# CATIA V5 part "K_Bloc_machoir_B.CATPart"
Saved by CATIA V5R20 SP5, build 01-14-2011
Part number: bloc_machoir_2
Publications: "diam_trou_fourreau"
Bounding box of the stored display mesh (mm): x -55.068 to 17.929, y -56.771 to 28.229, z 0 to 35
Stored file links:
  G:\Khaled_CFAO_2011\SIL\SIL_GR1\mroland\Khaled\CAD_CATIA_Modifie\K_Bloc_machoir_B.CATPart
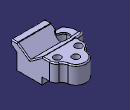
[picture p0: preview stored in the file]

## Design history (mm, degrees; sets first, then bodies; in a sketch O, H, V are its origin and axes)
Parameters
  diam_trou_fourreau = 22 mm
Set1
  Sketch1 on xy-plane, origin (0, 0, 0), H (1, 0, 0), V (0, 1, 0)
    point P1 (-32.0711, 0)
    line L1 (-32.0711, -56.7712) -> (17.9289, -56.7712)
    line L2 (17.9289, -56.7712) -> (17.9289, 0)
    point P4 (17.9289, 0)
    arc A1 centre (7.9289, 0) radius 10 from (17.9289, 0) to (13.0826, 8.5697) ccw
    point P5 (7.9289, 0)
    point P6 (17.9289, 0)
    arc A2 centre (-7.0711, 13.2288) radius 15 from (7.6161, 16.276) to (-21.9589, 15.0594) ccw
    point P7 (-7.0711, 13.2288)
    point P8 (0, 26.4575)
    arc A3 centre (-22.0711, 0) radius 10 from (-26.3136, 9.0554) to (-32.0711, 0) ccw
    point P9 (-22.0711, 0)
    point P10 (-32.0711, 0)
    arc A4 centre (-29.5647, 15.9947) radius 7.6631 from (-21.9589, 15.0594) to (-26.3136, 9.0554) cw
    arc A5 centre (19.1569, 18.6704) radius 11.7865 from (7.6161, 16.276) to (13.0826, 8.5697) ccw
    line L3 (-32.0711, -56.7712) -> (-32.0711, -52.5474)
    arc A6 centre (-35.0711, -32.7737) radius 20 from (-32.0711, -52.5474) to (-32.0711, -13) cw
    point P18 (-35.0711, -32.7737)
    point P19 (-32.0711, -13)
    line L4 (-32.0711, -13) -> (-32.0711, 0)
    distance P9 A3 = 10
    distance P5 A1 = 10
    distance P7 A2 = 15
    distance P7 P9 = 20
    distance P7 P5 = 20
    distance P5 P9 = 30
    distance L1 A2 = 85
    radius A4 = 7.6631
    radius A5 = 11.7865
    radius A6 = 20
    length L4 = 13
    distance P18 L4 = 3
    length L3 = 4.2238
    coincidence: P1 H, P4 H, A1 P6, P6 L2, A2 P8, P8 V, A2 O, A3 P10, P19 L3
    horizontal: L1 H
    vertical: L2 V
    tangency: L2 A1, A4 A2, A4 A3, A5 A2, A5 A1, L3 A3, L4 A3
Body1 (main body)
  Pad1: profile Sketch1, direction (0, 0, 1), length 35
  Sketch2 on end face of Pad1, origin (-8.9228, 9.7204, 35), H (1, 0, 0), V (0, 1, 0)
    point P1 (1.8517, 3.5083)
    reference projected arc E1 centre (1.8517, 3.5083) radius 15 from (16.5389, 6.5556) to (-13.0362, 5.339) ccw from edge [face of Pad1 from Sketch1.A2 | end face of Pad1]
    concentricity: E1 P1
  Hole1: placed by Sketch2, at (-7.0711, 13.2288, 35) direction (0, 0, -1), diameter 10 {= 10mm}, through (limit type 3)
  Sketch3 on end face of Pad1, origin (-21.1049, 2.0333, 35), H (1, 0, 0), V (0, 1, 0)
    point P1 (28.4106, -1.4836)
    reference projected point E1 (14.0338, 11.1955) from axis of face of Hole1
    distance E1 P1 = 19.169
  Hole2: placed by Sketch3, at (7.3057, 0.5497, 35) direction (0, 0, -1), diameter 10, through (limit type 3)
  Sketch4 on end face of Pad1, origin (-9.8751, -18.0882, 35), H (1, 0, 0), V (0, 1, 0)
    point P1 (-12.8071, 19.4905)
    reference projected point E1 (17.1807, 18.6379) from axis of face of Hole2
    reference projected point E2 (2.804, 31.317) from axis of face of Hole1
    distance P1 E1 = 30
    distance P1 E2 = 19.585
    distance P1 H = 19.3485
  Hole3: placed by Sketch4, at (-22.6822, 1.4023, 35) direction (0, 0, -1), diameter 10, through (limit type 3)
  Sketch5 on start face of Pad1, origin (-3.6482, -28.1007, 0), H (1, 0, 0), V (0, -1, 0)
    point P1 (-31.4229, 4.673)
    reference projected arc E1 centre (-31.4229, 4.673) radius 20 from (-28.4229, 24.4468) to (-28.4229, -15.1007) ccw from edge [start face of Pad1 | face of Pad1 from Sketch1.A6]
    concentricity: E1 P1
  Hole4: placed by Sketch5, at (-35.0711, -32.7737, 0) direction (0, 0, 1), diameter 22 {= diam_trou_fourreau}, depth 20
  Sketch6 on start face of Pad1, origin (-39.0223, -19.3557, 0), H (1, 0, 0), V (0, -1, 0)
    point P1 (3.9512, 13.418)
    reference projected circle E1 centre (3.9512, 13.418) radius 11 from edge [face of Hole4 | start face of Pad1]
    concentricity: E1 P1
  Hole5: placed by Sketch6, at (-35.0711, -32.7737, 0) direction (0, 0, 1), diameter 18, through (limit type 3)
  Sketch7 on start face of Pad1, origin (0, 0, 0), H (1, 0, 0), V (0, -1, 0)
    line L1 (-37.0711, 10.7737) -> (22.9289, 10.7737)
    line L2 (22.9289, 10.7737) -> (22.9289, -33.2288)
    line L3 (22.9289, -33.2288) -> (-37.0711, -33.2288)
    line L4 (-37.0711, -33.2288) -> (-37.0711, 10.7737)
    reference projected arc E1 centre (-35.0711, 32.7737) radius 20 from (-32.0711, 52.5474) to (-32.0711, 13) ccw from edge [start face of Pad1 | face of Pad1 from Sketch1.A6]
    reference projected line E2 (17.9289, 56.7712) -> (17.9289, 0) from edge [start face of Pad1 | face of Pad1 from Sketch1.L2]
    reference projected line E3 (-32.0711, 0) -> (-32.0711, 13) from edge [start face of Pad1 | face of Pad1 from Sketch1.L4]
    reference projected arc E4 centre (-7.0711, -13.2288) radius 15 from (-21.9589, -15.0594) to (7.6161, -16.276) ccw from edge [start face of Pad1 | face of Pad1 from Sketch1.A2]
    distance E1 L1 = 2
    distance L2 E2 = 5
    distance E3 L4 = 5
    distance E4 L3 = 5
    horizontal: L1 H, L3 H
    vertical: L2 V, L4 V
  Pocket1: profile Sketch7, direction (0, 0, 1), length 10
  Sketch8 on face of Pad1 from Sketch1.L2, origin (17.9289, 0, 0), H (0, 1, 0), V (0, 0, 1)
    line L1 (-56.7712, 35) -> (-46.7712, 35)
    point P2 (-46.7712, 35)
    line L2 (-46.7712, 35) -> (-28.7712, 22.3509)
    line L3 (-28.7712, 22.3509) -> (-10.7712, 35)
    point P4 (-10.7712, 35)
    line L4 (-10.7712, 35) -> (3.2288, 35)
    line L5 (3.2288, 35) -> (3.2288, 40)
    line L6 (3.2288, 40) -> (-56.7712, 40)
    line L7 (-56.7712, 40) -> (-56.7712, 35)
    reference projected line E1 (-56.7712, 0) -> (-56.7712, 35) from edge [face of Pad1 from Sketch1.L2 | face of Pad1 from Sketch1.L1]
    reference projected line E2 (-56.7712, 35) -> (0, 35) from edge [face of Pad1 from Sketch1.L2 | end face of Pad1]
    reference projected line E3 (-56.7712, 35) -> (0, 35) from edge [face of Pad1 from Sketch1.L2 | end face of Pad1]
    length L1 = 10
    length L2 = 22
    length L3 = 22
    distance P2 P4 = 36
    length L6 = 60
    length L5 = 5
    horizontal: L1 H, L4 H, L6 H
    coincidence: P4 L1, L7 E1, L1 E2, L4 E3
    vertical: L5 V, L7 V
  Pocket2: profile Sketch8, direction (-1, 0, 0), through (limit type 3)
  Sketch9 on end face of Pad1, origin (0, 0, 35), H (1, 0, 0), V (0, 1, 0)
    line L1 (-32.0711, -56.7712) -> (-32.0711, -28.7712)
    line L2 (-32.0711, -28.7712) -> (-55.0711, -28.7712)
    line L3 (-55.0711, -28.7712) -> (-55.0711, -56.7712)
    line L4 (-55.0711, -56.7712) -> (-32.0711, -56.7712)
    reference projected line E1 (17.9289, -56.7712) -> (-32.0711, -56.7712) from edge [end face of Pad1 | face of Pad1 from Sketch1.L1]
    reference projected line E2 (-32.0711, -52.5474) -> (-32.0711, -56.7712) from edge [face of Pad1 from Sketch1.L3 | end face of Pad1]
    reference projected arc E3 centre (-35.0711, -32.7737) radius 20 from (-54.6665, -28.7712) to (-49.3564, -46.7712) ccw from edge [face of Pocket2 from Sketch8.L2 | face of Pad1 from Sketch1.A6]
    reference projected line E4 (-43.1321, -28.7712) -> (-54.6665, -28.7712) from edge [face of Pocket2 from Sketch8.L2 | face of Pocket2 from Sketch8.L3]
    vertical: L1 V, L3 V
    horizontal: L2 H
    coincidence: L4 E1, L1 E2, E4 L2
    tangency: E3 L3
  Pocket3: profile Sketch9, direction (0, 0, -1), length 13
  Sketch10 on face of Pad1 from Sketch1.L2, origin (17.9289, 0, 0), H (0, 1, 0), V (0, 0, 1)
    point P1 (-56.7712, 28)
    line L1 (-56.7712, 28) -> (-48.7712, 22)
    line L2 (-48.7712, 22) -> (-48.7712, 0)
    point P3 (-48.7712, 0)
    line L3 (-48.7712, 0) -> (-56.7712, 0)
    line L4 (-56.7712, 0) -> (-56.7712, 28)
    reference projected line E1 (-56.7712, 0) -> (0, 0) from edge [start face of Pad1 | face of Pad1 from Sketch1.L2]
    reference projected line E2 (-56.7712, 0) -> (-56.7712, 35) from edge [face of Pad1 from Sketch1.L2 | face of Pad1 from Sketch1.L1]
    reference projected line E3 (-56.7712, 35) -> (0, 35) from edge [face of Pad1 from Sketch1.L2 | end face of Pad1]
    length L2 = 22
    distance E3 P1 = 7
    length L3 = 8
    coincidence: P3 H, E1 L3, L4 E2
    vertical: L2 V, L4 V
    horizontal: L3 H
  Pocket4: profile Sketch10, direction (-1, 0, 0), through (limit type 3)
  Fillet1: radius 1.5, on edge [face of Pad1 from Sketch1.A1 | end face of Pad1]; edge [face of Pad1 from Sketch1.A5 | end face of Pad1]; edge [face of Pad1 from Sketch1.A2 | end face of Pad1]; edge [face of Pad1 from Sketch1.A4 | end face of Pad1]; edge [face of Pad1 from Sketch1.A3 | end face of Pad1]; edge [face of Pad1 from Sketch1.L4 | end face of Pad1]; edge [face of Pad1 from Sketch1.L2 | end face of Pad1] (x2); edge [end face of Pad1 | face of Pocket2 from Sketch8.L3]; edge [face of Pad1 from Sketch1.L4 | face of Pocket2 from Sketch8.L3]; edge [face of Pad1 from Sketch1.L2 | face of Pocket2 from Sketch8.L3]; edge [face of Pad1 from Sketch1.L2 | face of Pocket2 from Sketch8.L2]; edge [face of Pocket2 from Sketch8.L2 | end face of Pad1]; edge [face of Pad1 from Sketch1.A6 | face of Pocket2 from Sketch8.L3]; edge [end face of Pad1 | face of Pad1 from Sketch1.L1]; edge [end face of Pad1 | face of Pocket3]; edge [face of Pocket2 from Sketch8.L2 | face of Pocket3]; edge [face of Pad1 from Sketch1.A6 | end face of Pocket3]; edge [face of Pocket2 from Sketch8.L3 | face of Pocket3 from Sketch9.L2]; edge [end face of Pocket3 | face of Pocket4 from Sketch10.L2]; edge [face of Pocket3 | face of Pocket4 from Sketch10.L1]; edge [face of Pad1 from Sketch1.L1 | face of Pocket3]
  Fillet2: radius 3, on edge [face of Pocket3 | end face of Pocket3]
  Fillet3: radius 5, on edge [face of Pad1 from Sketch1.A6 | face of Pocket4 from Sketch10.L2]
  Fillet4: radius 1.5, on edge [face of Pad1 from Sketch1.L2 | face of Pad1 from Sketch1.L1]; edge [face of Pad1 from Sketch1.L2 | face of Pocket4 from Sketch10.L1]; edge [face of Pad1 from Sketch1.L2 | face of Pocket4 from Sketch10.L2]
